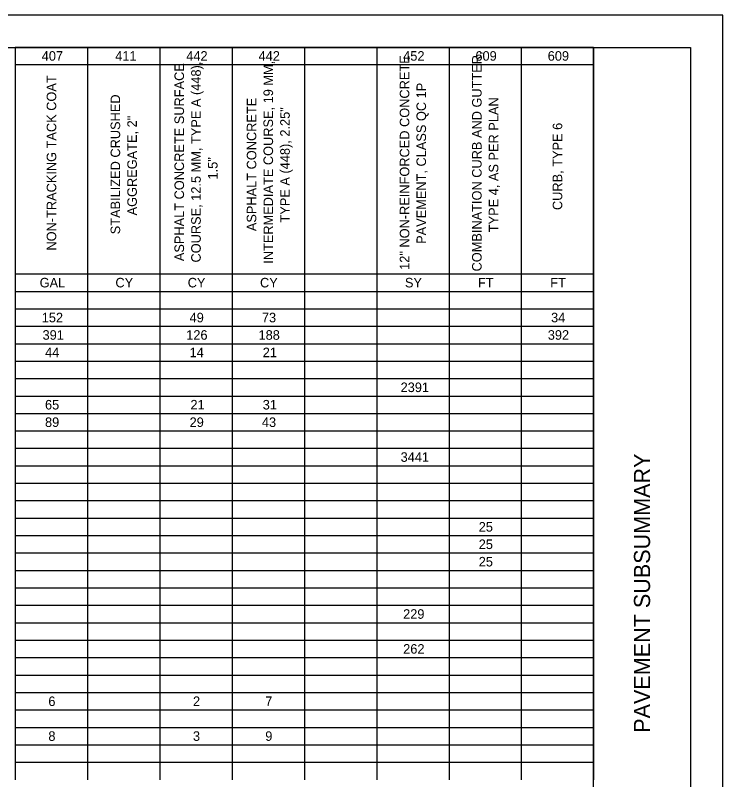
# Model space of a CAD drawing. Extents: x 0 to 34, y 0 to 22.
# Drawn here: x 23.04 to 34, y 10.15 to 22 of the extents above; entities that cross this region are included whole.
import ezdxf

# ---------------------------------------------------------------- set-up
doc = ezdxf.new("R2010")
doc.units = 0
for name, color, linetype in [('SH_Border', 7, 'Continuous'), ('SH_Cut_Line', 7, 'Continuous'), ('SH_Data', 7, 'Continuous'), ('SH_Text', 7, 'Continuous')]:
    doc.layers.add(name, color=color, linetype=linetype)

msp = doc.modelspace()

# ---------------------------------------------------------------- linework, layer by layer
at = {"layer": 'SH_Border'}
msp.add_line((32, 0.5), (32, 21.5), dxfattribs=at)
msp.add_lwpolyline([(1.5, 21.5), (33.5, 21.5), (33.5, 0.5), (1.5, 0.5)], close=True, dxfattribs=at)
at = {"layer": 'SH_Cut_Line'}
msp.add_lwpolyline([(0, 0), (34, 0), (34, 22), (0, 22)], close=True, dxfattribs=at)
at = {"layer": 'SH_Text'}
for p, q in [((23.041, 21.505), (24.161, 21.505)), ((23.041, 21.505), (23.041, 21.235)), ((24.161, 21.505), (27.52, 21.505)), ((24.161, 21.505), (24.161, 21.235)), ((25.28, 21.505), (25.28, 21.235)), ((26.4, 21.505), (26.4, 21.235)), ((27.52, 21.505), (29.76, 21.505)), ((27.52, 21.505), (27.52, 21.235)), ((28.64, 21.505), (28.64, 21.235)), ((29.76, 21.505), (32, 21.505)), ((29.76, 21.505), (29.76, 21.235)), ((30.88, 21.505), (30.88, 21.235)), ((32, 21.505), (32, 21.235)), ((23.041, 21.235), (24.161, 21.235)), ((23.041, 21.235), (23.041, 20.965)), ((24.161, 21.235), (27.52, 21.235)), ((24.161, 21.235), (24.161, 20.965)), ((25.28, 21.235), (25.28, 20.965)), ((26.4, 21.235), (26.4, 20.965)), ((27.52, 21.235), (29.76, 21.235)), ((27.52, 21.235), (27.52, 20.965)), ((28.64, 21.235), (28.64, 20.965)), ((29.76, 21.235), (32, 21.235)), ((29.76, 21.235), (29.76, 20.965)), ((30.88, 21.235), (30.88, 20.965)), ((32, 21.235), (32, 20.965)), ((23.041, 20.965), (23.041, 20.694)), ((24.161, 20.965), (24.161, 20.694)), ((25.28, 20.965), (25.28, 20.694)), ((26.4, 20.965), (26.4, 20.694)), ((27.52, 20.965), (27.52, 20.694)), ((28.64, 20.965), (28.64, 20.694)), ((29.76, 20.965), (29.76, 20.694)), ((30.88, 20.965), (30.88, 20.694)), ((32, 20.965), (32, 20.694)), ((23.041, 20.694), (23.041, 20.154)), ((24.161, 20.694), (24.161, 20.154)), ((25.28, 20.694), (25.28, 20.154)), ((26.4, 20.694), (26.4, 20.154)), ((27.52, 20.694), (27.52, 20.154)), ((28.64, 20.694), (28.64, 20.154)), ((29.76, 20.694), (29.76, 20.154)), ((30.88, 20.694), (30.88, 20.154)), ((32, 20.694), (32, 20.154)), ((23.041, 20.154), (23.041, 19.883)), ((24.161, 20.154), (24.161, 19.883)), ((25.28, 20.154), (25.28, 19.883)), ((26.4, 20.154), (26.4, 19.883)), ((27.52, 20.154), (27.52, 19.883)), ((28.64, 20.154), (28.64, 19.883)), ((29.76, 20.154), (29.76, 19.883)), ((30.88, 20.154), (30.88, 19.883)), ((32, 20.154), (32, 19.883)), ((23.041, 19.883), (23.041, 19.613)), ((24.161, 19.883), (24.161, 19.613)), ((25.28, 19.883), (25.28, 19.613)), ((26.4, 19.883), (26.4, 19.613)), ((27.52, 19.883), (27.52, 19.613)), ((28.64, 19.883), (28.64, 19.613)), ((29.76, 19.883), (29.76, 19.613)), ((30.88, 19.883), (30.88, 19.613)), ((32, 19.883), (32, 19.613)), ((23.041, 19.613), (23.041, 19.343)), ((24.161, 19.613), (24.161, 19.343)), ((25.28, 19.613), (25.28, 19.343)), ((26.4, 19.613), (26.4, 19.343)), ((27.52, 19.613), (27.52, 19.343)), ((28.64, 19.613), (28.64, 19.343)), ((29.76, 19.613), (29.76, 19.343)), ((30.88, 19.613), (30.88, 19.343)), ((32, 19.613), (32, 19.343)), ((23.041, 19.343), (23.041, 19.072)), ((24.161, 19.343), (24.161, 19.072)), ((25.28, 19.343), (25.28, 19.072)), ((26.4, 19.343), (26.4, 19.072)), ((27.52, 19.343), (27.52, 19.072)), ((28.64, 19.343), (28.64, 19.072)), ((29.76, 19.343), (29.76, 19.072)), ((30.88, 19.343), (30.88, 19.072)), ((32, 19.343), (32, 19.072)), ((23.041, 19.072), (23.041, 18.802)), ((24.161, 19.072), (24.161, 18.802)), ((25.28, 19.072), (25.28, 18.802)), ((26.4, 19.072), (26.4, 18.802)), ((27.52, 19.072), (27.52, 18.802)), ((28.64, 19.072), (28.64, 18.802)), ((29.76, 19.072), (29.76, 18.802)), ((30.88, 19.072), (30.88, 18.802)), ((32, 19.072), (32, 18.802)), ((23.041, 18.802), (23.041, 18.532)), ((24.161, 18.802), (24.161, 18.532)), ((25.28, 18.802), (25.28, 18.532)), ((26.4, 18.802), (26.4, 18.532)), ((27.52, 18.802), (27.52, 18.532)), ((28.64, 18.802), (28.64, 18.532)), ((29.76, 18.802), (29.76, 18.532)), ((30.88, 18.802), (30.88, 18.532)), ((32, 18.802), (32, 18.532)), ((23.041, 18.532), (23.041, 18.262)), ((24.161, 18.532), (24.161, 18.262)), ((25.28, 18.532), (25.28, 18.262)), ((26.4, 18.532), (26.4, 18.262)), ((27.52, 18.532), (27.52, 18.262)), ((28.64, 18.532), (28.64, 18.262)), ((29.76, 18.532), (29.76, 18.262)), ((30.88, 18.532), (30.88, 18.262)), ((32, 18.532), (32, 18.262)), ((23.041, 18.262), (23.041, 17.991)), ((24.161, 18.262), (24.161, 17.991)), ((25.28, 18.262), (25.28, 17.991)), ((26.4, 18.262), (26.4, 17.991)), ((27.52, 18.262), (27.52, 17.991)), ((28.64, 18.262), (28.64, 17.991)), ((29.76, 18.262), (29.76, 17.991)), ((30.88, 18.262), (30.88, 17.991)), ((32, 18.262), (32, 17.991)), ((23.041, 17.991), (24.161, 17.991)), ((23.041, 17.991), (23.041, 17.721)), ((24.161, 17.991), (27.52, 17.991)), ((24.161, 17.991), (24.161, 17.721)), ((25.28, 17.991), (25.28, 17.721)), ((26.4, 17.991), (26.4, 17.721)), ((27.52, 17.991), (29.76, 17.991)), ((27.52, 17.991), (27.52, 17.721)), ((28.64, 17.991), (28.64, 17.721)), ((29.76, 17.991), (32, 17.991)), ((29.76, 17.991), (29.76, 17.721)), ((30.88, 17.991), (30.88, 17.721)), ((32, 17.991), (32, 17.721)), ((23.041, 17.721), (24.161, 17.721)), ((23.041, 17.721), (23.041, 17.451)), ((24.161, 17.721), (27.52, 17.721)), ((24.161, 17.721), (24.161, 17.451)), ((25.28, 17.721), (25.28, 17.451)), ((26.4, 17.721), (26.4, 17.451)), ((27.52, 17.721), (29.76, 17.721)), ((27.52, 17.721), (27.52, 17.451)), ((28.64, 17.721), (28.64, 17.451)), ((29.76, 17.721), (32, 17.721)), ((29.76, 17.721), (29.76, 17.451)), ((30.88, 17.721), (30.88, 17.451)), ((32, 17.721), (32, 17.451)), ((23.041, 17.451), (24.161, 17.451)), ((23.041, 17.451), (23.041, 17.18)), ((24.161, 17.451), (27.52, 17.451)), ((24.161, 17.451), (24.161, 17.18)), ((25.28, 17.451), (25.28, 17.18)), ((26.4, 17.451), (26.4, 17.18)), ((27.52, 17.451), (29.76, 17.451)), ((27.52, 17.451), (27.52, 17.18)), ((28.64, 17.451), (28.64, 17.18)), ((29.76, 17.451), (32, 17.451)), ((29.76, 17.451), (29.76, 17.18)), ((30.88, 17.451), (30.88, 17.18)), ((32, 17.451), (32, 17.18)), ((23.041, 17.18), (24.161, 17.18)), ((23.041, 17.18), (23.041, 16.91)), ((24.161, 17.18), (27.52, 17.18)), ((24.161, 17.18), (24.161, 16.91)), ((25.28, 17.18), (25.28, 16.91)), ((26.4, 17.18), (26.4, 16.91)), ((27.52, 17.18), (29.76, 17.18)), ((27.52, 17.18), (27.52, 16.91)), ((28.64, 17.18), (28.64, 16.91)), ((29.76, 17.18), (32, 17.18)), ((29.76, 17.18), (29.76, 16.91)), ((30.88, 17.18), (30.88, 16.91)), ((32, 17.18), (32, 16.91)), ((23.041, 16.91), (24.161, 16.91)), ((23.041, 16.91), (23.041, 16.369)), ((24.161, 16.91), (27.52, 16.91)), ((24.161, 16.91), (24.161, 16.369)), ((25.28, 16.91), (25.28, 16.369)), ((26.4, 16.91), (26.4, 16.369)), ((27.52, 16.91), (29.76, 16.91)), ((27.52, 16.91), (27.52, 16.369)), ((28.64, 16.91), (28.64, 16.369)), ((29.76, 16.91), (32, 16.91)), ((29.76, 16.91), (29.76, 16.369)), ((30.88, 16.91), (30.88, 16.369)), ((32, 16.91), (32, 16.369)), ((23.041, 16.64), (24.161, 16.64)), ((24.161, 16.64), (27.52, 16.64)), ((27.52, 16.64), (29.76, 16.64)), ((29.76, 16.64), (32, 16.64)), ((23.041, 16.369), (24.161, 16.369)), ((23.041, 16.369), (23.041, 16.099)), ((24.161, 16.369), (27.52, 16.369)), ((24.161, 16.369), (24.161, 16.099)), ((25.28, 16.369), (25.28, 16.099)), ((26.4, 16.369), (26.4, 16.099)), ((27.52, 16.369), (29.76, 16.369)), ((27.52, 16.369), (27.52, 16.099)), ((28.64, 16.369), (28.64, 16.099)), ((29.76, 16.369), (32, 16.369)), ((29.76, 16.369), (29.76, 16.099)), ((30.88, 16.369), (30.88, 16.099)), ((32, 16.369), (32, 16.099)), ((23.041, 16.099), (24.161, 16.099)), ((23.041, 16.099), (23.041, 15.829)), ((24.161, 16.099), (27.52, 16.099)), ((24.161, 16.099), (24.161, 15.829)), ((25.28, 16.099), (25.28, 15.829)), ((26.4, 16.099), (26.4, 15.829)), ((27.52, 16.099), (29.76, 16.099)), ((27.52, 16.099), (27.52, 15.829)), ((28.64, 16.099), (28.64, 15.829)), ((29.76, 16.099), (32, 16.099)), ((29.76, 16.099), (29.76, 15.829)), ((30.88, 16.099), (30.88, 15.829)), ((32, 16.099), (32, 15.829)), ((23.041, 15.829), (24.161, 15.829)), ((23.041, 15.829), (23.041, 15.558)), ((24.161, 15.829), (27.52, 15.829)), ((24.161, 15.829), (24.161, 15.558)), ((25.28, 15.829), (25.28, 15.558)), ((26.4, 15.829), (26.4, 15.558)), ((27.52, 15.829), (29.76, 15.829)), ((27.52, 15.829), (27.52, 15.558)), ((28.64, 15.829), (28.64, 15.558)), ((29.76, 15.829), (32, 15.829)), ((29.76, 15.829), (29.76, 15.558)), ((30.88, 15.829), (30.88, 15.558)), ((32, 15.829), (32, 15.558)), ((23.041, 15.558), (24.161, 15.558)), ((23.041, 15.558), (23.041, 15.018)), ((24.161, 15.558), (27.52, 15.558)), ((24.161, 15.558), (24.161, 15.018)), ((25.28, 15.558), (25.28, 15.018)), ((26.4, 15.558), (26.4, 15.018)), ((27.52, 15.558), (29.76, 15.558)), ((27.52, 15.558), (27.52, 15.018)), ((28.64, 15.558), (28.64, 15.018)), ((29.76, 15.558), (32, 15.558)), ((29.76, 15.558), (29.76, 15.018)), ((30.88, 15.558), (30.88, 15.018)), ((32, 15.558), (32, 15.018)), ((23.041, 15.288), (24.161, 15.288)), ((24.161, 15.288), (27.52, 15.288)), ((27.52, 15.288), (29.76, 15.288)), ((29.76, 15.288), (32, 15.288)), ((23.041, 15.018), (24.161, 15.018)), ((23.041, 15.018), (23.041, 14.747)), ((24.161, 15.018), (27.52, 15.018)), ((24.161, 15.018), (24.161, 14.747)), ((25.28, 15.018), (25.28, 14.747)), ((26.4, 15.018), (26.4, 14.747)), ((27.52, 15.018), (29.76, 15.018)), ((27.52, 15.018), (27.52, 14.747)), ((28.64, 15.018), (28.64, 14.747)), ((29.76, 15.018), (32, 15.018)), ((29.76, 15.018), (29.76, 14.747)), ((30.88, 15.018), (30.88, 14.747)), ((32, 15.018), (32, 14.747)), ((23.041, 14.747), (24.161, 14.747)), ((23.041, 14.747), (23.041, 14.477)), ((24.161, 14.747), (27.52, 14.747)), ((24.161, 14.747), (24.161, 14.477)), ((25.28, 14.747), (25.28, 14.477)), ((26.4, 14.747), (26.4, 14.477)), ((27.52, 14.747), (29.76, 14.747)), ((27.52, 14.747), (27.52, 14.477)), ((28.64, 14.747), (28.64, 14.477)), ((29.76, 14.747), (32, 14.747)), ((29.76, 14.747), (29.76, 14.477)), ((30.88, 14.747), (30.88, 14.477)), ((32, 14.747), (32, 14.477)), ((23.041, 14.477), (24.161, 14.477)), ((23.041, 14.477), (23.041, 14.207)), ((24.161, 14.477), (27.52, 14.477)), ((24.161, 14.477), (24.161, 14.207)), ((25.28, 14.477), (25.28, 14.207)), ((26.4, 14.477), (26.4, 14.207)), ((27.52, 14.477), (29.76, 14.477)), ((27.52, 14.477), (27.52, 14.207)), ((28.64, 14.477), (28.64, 14.207)), ((29.76, 14.477), (32, 14.477)), ((29.76, 14.477), (29.76, 14.207)), ((30.88, 14.477), (30.88, 14.207)), ((32, 14.477), (32, 14.207)), ((23.041, 14.207), (24.161, 14.207)), ((23.041, 14.207), (23.041, 13.396)), ((24.161, 14.207), (27.52, 14.207)), ((24.161, 14.207), (24.161, 13.396)), ((25.28, 14.207), (25.28, 13.396)), ((26.4, 14.207), (26.4, 13.396)), ((27.52, 14.207), (29.76, 14.207)), ((27.52, 14.207), (27.52, 13.396)), ((28.64, 14.207), (28.64, 13.396)), ((29.76, 14.207), (32, 14.207)), ((29.76, 14.207), (29.76, 13.396)), ((30.88, 14.207), (30.88, 13.396)), ((32, 14.207), (32, 13.396)), ((23.041, 13.936), (24.161, 13.936)), ((24.161, 13.936), (27.52, 13.936)), ((27.52, 13.936), (29.76, 13.936)), ((29.76, 13.936), (32, 13.936)), ((23.041, 13.666), (24.161, 13.666)), ((24.161, 13.666), (27.52, 13.666)), ((27.52, 13.666), (29.76, 13.666)), ((29.76, 13.666), (32, 13.666)), ((23.041, 13.396), (24.161, 13.396)), ((23.041, 13.396), (23.041, 13.125)), ((24.161, 13.396), (27.52, 13.396)), ((24.161, 13.396), (24.161, 13.125)), ((25.28, 13.396), (25.28, 13.125)), ((26.4, 13.396), (26.4, 13.125)), ((27.52, 13.396), (29.76, 13.396)), ((27.52, 13.396), (27.52, 13.125)), ((28.64, 13.396), (28.64, 13.125)), ((29.76, 13.396), (32, 13.396)), ((29.76, 13.396), (29.76, 13.125)), ((30.88, 13.396), (30.88, 13.125)), ((32, 13.396), (32, 13.125)), ((23.041, 13.125), (24.161, 13.125)), ((23.041, 13.125), (23.041, 12.044)), ((24.161, 13.125), (27.52, 13.125)), ((24.161, 13.125), (24.161, 12.044)), ((25.28, 13.125), (25.28, 12.044)), ((26.4, 13.125), (26.4, 12.044)), ((27.52, 13.125), (29.76, 13.125)), ((27.52, 13.125), (27.52, 12.044)), ((28.64, 13.125), (28.64, 12.044)), ((29.76, 13.125), (32, 13.125)), ((29.76, 13.125), (29.76, 12.044)), ((30.88, 13.125), (30.88, 12.044)), ((32, 13.125), (32, 12.044)), ((23.041, 12.855), (24.161, 12.855)), ((24.161, 12.855), (27.52, 12.855)), ((27.52, 12.855), (29.76, 12.855)), ((29.76, 12.855), (32, 12.855)), ((23.041, 12.585), (24.161, 12.585)), ((24.161, 12.585), (27.52, 12.585)), ((27.52, 12.585), (29.76, 12.585)), ((29.76, 12.585), (32, 12.585)), ((23.041, 12.314), (24.161, 12.314)), ((24.161, 12.314), (27.52, 12.314)), ((27.52, 12.314), (29.76, 12.314)), ((29.76, 12.314), (32, 12.314)), ((23.041, 12.044), (24.161, 12.044)), ((23.041, 12.044), (23.041, 11.774)), ((24.161, 12.044), (27.52, 12.044)), ((24.161, 12.044), (24.161, 11.774)), ((25.28, 12.044), (25.28, 11.774)), ((26.4, 12.044), (26.4, 11.774)), ((27.52, 12.044), (29.76, 12.044)), ((27.52, 12.044), (27.52, 11.774)), ((28.64, 12.044), (28.64, 11.774)), ((29.76, 12.044), (32, 12.044)), ((29.76, 12.044), (29.76, 11.774)), ((30.88, 12.044), (30.88, 11.774)), ((32, 12.044), (32, 11.774)), ((23.041, 11.774), (24.161, 11.774)), ((23.041, 11.774), (23.041, 10.692)), ((24.161, 11.774), (27.52, 11.774)), ((24.161, 11.774), (24.161, 10.692)), ((25.28, 11.774), (25.28, 10.692)), ((26.4, 11.774), (26.4, 10.692)), ((27.52, 11.774), (29.76, 11.774)), ((27.52, 11.774), (27.52, 10.692)), ((28.64, 11.774), (28.64, 10.692)), ((29.76, 11.774), (32, 11.774)), ((29.76, 11.774), (29.76, 10.692)), ((30.88, 11.774), (30.88, 10.692)), ((32, 11.774), (32, 10.692)), ((23.041, 11.503), (24.161, 11.503)), ((24.161, 11.503), (27.52, 11.503)), ((27.52, 11.503), (29.76, 11.503)), ((29.76, 11.503), (32, 11.503)), ((23.041, 11.233), (24.161, 11.233)), ((24.161, 11.233), (27.52, 11.233)), ((27.52, 11.233), (29.76, 11.233)), ((29.76, 11.233), (32, 11.233)), ((23.041, 10.963), (24.161, 10.963)), ((24.161, 10.963), (27.52, 10.963)), ((27.52, 10.963), (29.76, 10.963)), ((29.76, 10.963), (32, 10.963)), ((23.041, 10.692), (24.161, 10.692)), ((23.041, 10.692), (23.041, 10.152)), ((24.161, 10.692), (27.52, 10.692)), ((24.161, 10.692), (24.161, 10.152)), ((25.28, 10.692), (25.28, 10.152)), ((26.4, 10.692), (26.4, 10.152)), ((27.52, 10.692), (29.76, 10.692)), ((27.52, 10.692), (27.52, 10.152)), ((28.64, 10.692), (28.64, 10.152)), ((29.76, 10.692), (32, 10.692)), ((29.76, 10.692), (29.76, 10.152)), ((30.88, 10.692), (30.88, 10.152)), ((32, 10.692), (32, 10.152)), ((23.041, 10.422), (24.161, 10.422)), ((24.161, 10.422), (27.52, 10.422)), ((27.52, 10.422), (29.76, 10.422)), ((29.76, 10.422), (32, 10.422))]:
    msp.add_line(p, q, dxfattribs=at)

# ---------------------------------------------------------------- texts
at = {"layer": 'SH_Data'}
msp.add_text('PAVEMENT SUBSUMMARY', height=0.25, rotation=90, dxfattribs=at).set_placement((32.875, 10.879))
at = {"layer": 'SH_Text'}
for s, p in [('407', (23.45, 21.296)), ('442', (25.69, 21.296)), ('442', (26.81, 21.296)), ('452', (29.05, 21.296)), ('609', (30.169, 21.296)), ('609', (31.289, 21.296)), ('411', (24.589, 21.296)), ('GAL', (23.418, 17.782)), ('CY', (24.592, 17.782)), ('CY', (25.712, 17.782)), ('CY', (26.832, 17.782)), ('SY', (29.077, 17.782)), ('FT', (30.208, 17.782)), ('FT', (31.328, 17.782)), ('152', (23.45, 17.241)), ('49', (25.741, 17.241)), ('73', (26.861, 17.241)), ('34', (31.341, 17.241)), ('391', (23.463, 16.971)), ('126', (25.689, 16.971)), ('188', (26.809, 16.971)), ('392', (31.29, 16.971)), ('44', (23.502, 16.701)), ('14', (25.741, 16.701)), ('21', (26.874, 16.701)), ('2391', (29.01, 16.16)), ('65', (23.501, 15.89)), ('21', (25.754, 15.89)), ('31', (26.874, 15.89)), ('89', (23.501, 15.619)), ('29', (25.741, 15.619)), ('43', (26.861, 15.619)), ('3441', (29.01, 15.079)), ('25', (30.22, 13.997)), ('25', (30.22, 13.727)), ('25', (30.22, 13.457)), ('229', (29.049, 12.646)), ('262', (29.05, 12.105)), ('6', (23.553, 11.294)), ('2', (25.794, 11.294)), ('7', (26.913, 11.294)), ('8', (23.553, 10.754)), ('3', (25.793, 10.754)), ('9', (26.913, 10.754))]:
    msp.add_text(s, height=0.148, dxfattribs=at).set_placement(p)
for s, height, p in [('12" NON-REINFORCED CONCRETE ', 0.14804, (29.145, 18.054)), ('COMBINATION CURB AND GUTTER, ', 0.14804, (30.265, 18.03)), ('ASPHALT CONCRETE SURFACE ', 0.14804, (25.655, 18.189)), ('COURSE, 12.5 MM, TYPE A (448), ', 0.14804, (25.914, 18.168)), ('INTERMEDIATE COURSE, 19 MM, ', 0.14804, (27.034, 18.149)), ('NON-TRACKING TACK COAT', 0.14804, (23.675, 18.353)), ('PAVEMENT, CLASS QC 1P', 0.14804, (29.404, 18.457)), ('STABILIZED CRUSHED ', 0.14804, (24.665, 18.606)), ('ASPHALT CONCRETE ', 0.14804, (26.775, 18.654)), ('TYPE 4, AS PER PLAN', 0.14804, (30.524, 18.638)), ('TYPE A (448), 2.25"', 0.14804, (27.293, 18.788)), ('AGGREGATE, 2"', 0.14804, (24.924, 18.898)), ('CURB, TYPE 6', 0.14804, (31.514, 18.981)), ('1.5"', 0.148, (26.174, 19.455))]:
    msp.add_text(s, height=height, rotation=90, dxfattribs=at).set_placement(p)

doc.saveas('drawing.dxf')
